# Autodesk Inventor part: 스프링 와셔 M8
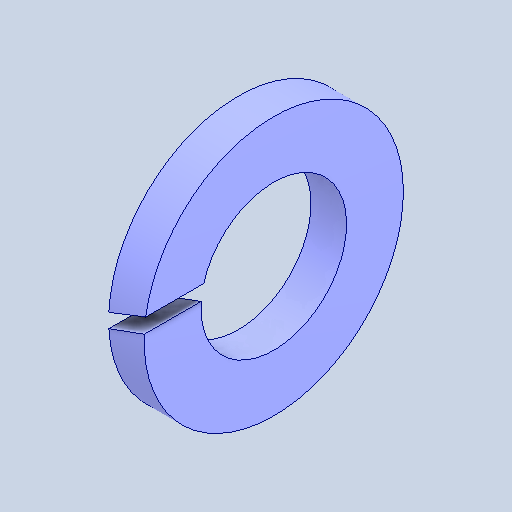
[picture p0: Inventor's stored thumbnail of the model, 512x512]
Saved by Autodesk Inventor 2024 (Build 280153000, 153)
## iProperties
Created: 2025-10
Part Number: 스프링 와셔 M8
Material: 강철, 연강
Description: 스프링 잠금 와셔
Document SubType Name: Modeling
Designer: EDU03
Density: 7.85 g/cm^3
Appearance: 기본값
Author: jhkim
Sending System: Autodesk Inventor 2026
Preprocessor: ST-DEVELOPER v20.1
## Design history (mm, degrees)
feature "Solid1"
node "솔리드1"
